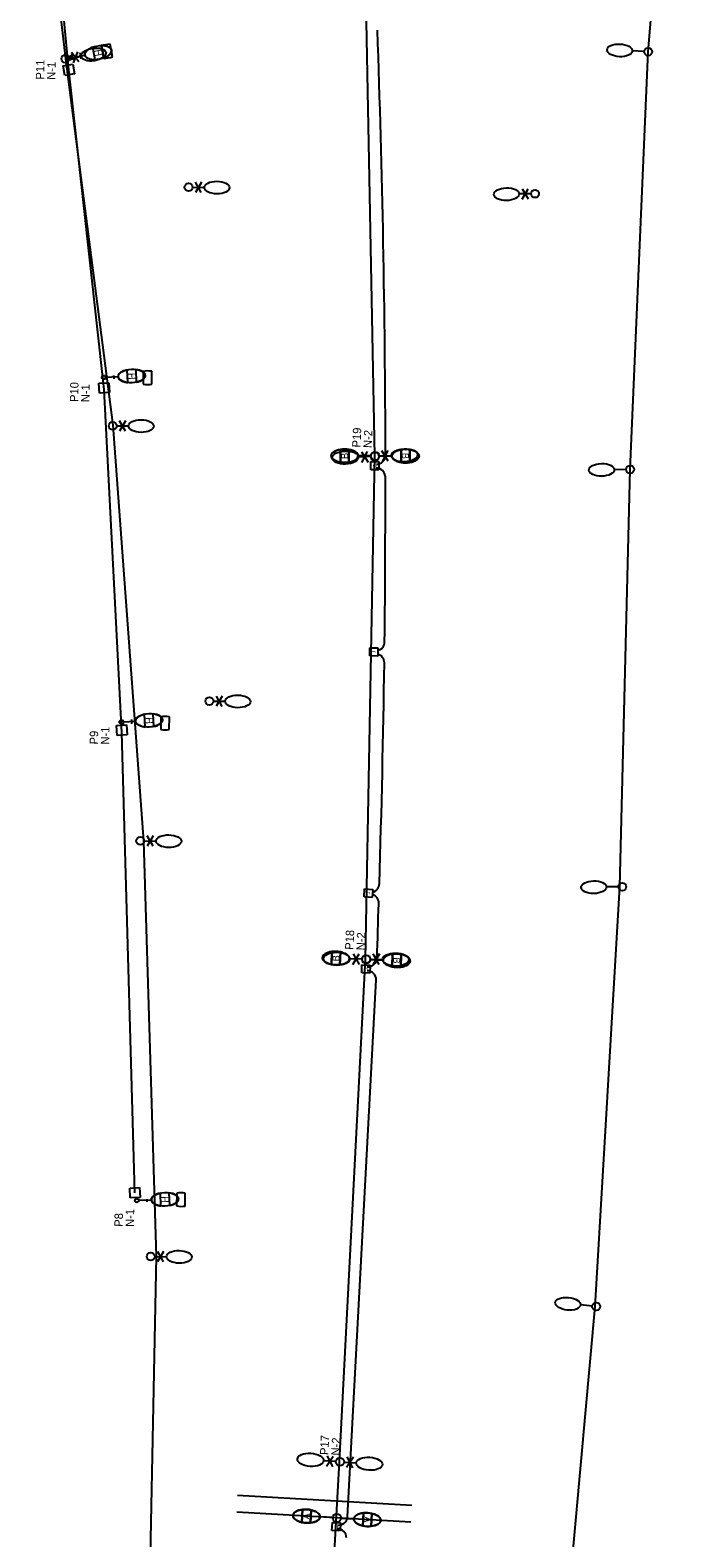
# Model space of a CAD drawing. Extents: x 925407 to 930994, y 604905 to 637063.
# Drawn here: x 929630 to 930028, y 609160 to 610061 of the extents above; entities that cross this region are included whole.
import ezdxf

# ---------------------------------------------------------------- set-up
doc = ezdxf.new("R2010")
doc.units = 0
for name, color, linetype in [('ActivePointCell_dp', 7, 'Continuous'), ('Conduit', 7, 'Continuous'), ('ConduitOT', 7, 'Continuous'), ('LiteCond_ep', 7, 'Continuous'), ('Miscellaneous2', 7, 'Continuous'), ('Miscellaneous9', 7, 'Continuous'), ('PoleLight', 7, 'Continuous'), ('PoleLight_ep', 7, 'Continuous'), ('PullBox', 7, 'Continuous')]:
    doc.layers.add(name, color=color, linetype=linetype)

msp = doc.modelspace()

# ---------------------------------------------------------------- linework, layer by layer
at = {"layer": 'ActivePointCell_dp'}
for p, q in [((929655.75, 610043.5), (929655.25, 610047.18)), ((929660.7, 610044.16), (929660.21, 610047.84)), ((929675.46, 609852.54), (929675.36, 609854.56)), ((929680.46, 609852.8), (929680.35, 609854.82)), ((929686.06, 609646.41), (929685.93, 609648.96)), ((929691.05, 609646.66), (929690.92, 609649.22)), ((929695.22, 609360.91), (929695.22, 609362.5)), ((929700.22, 609360.92), (929700.22, 609362.51)), ((929858.32, 609179.34), (929754.23, 609185.22)), ((929857.75, 609169.36), (929753.67, 609175.24))]:
    msp.add_line(p, q, dxfattribs=at)
at = {"layer": 'Conduit'}
for p, q in [((929999.47, 610048.38), (930027.95, 610398.52)), ((929988.71, 609798.68), (929999.47, 610048.38)), ((929982.61, 609549.14), (929988.71, 609798.68)), ((929967.83, 609298.26), (929982.61, 609549.14))]:
    msp.add_line(p, q, dxfattribs=at)
at = {"layer": 'ConduitOT'}
for p, q in [((929653.36, 610037.56), (929636.27, 610218.27)), ((929674.57, 609846.54), (929653.36, 610037.56)), ((929684.95, 609641.34), (929674.57, 609846.54)), ((929692.89, 609366.24), (929684.95, 609641.34)), ((929819.93, 609172.4), (929837.08, 609493.53))]:
    msp.add_line(p, q, dxfattribs=at)
for centre, radius, start, end in [((922203.17, 609789.01), 7639.44, 0.137669, 2.042639), ((929837.18, 609807.26), 5.5, 269.49023, 359.64309), ((929836.96, 609794.07), 5.5, 0.11193, 90.26479), ((922203.04, 609777.74), 7639.44, 359.384428, 0.122612), ((929836.54, 609695.73), 5.5, 285.60629, 359.29984), ((929836.38, 609683.07), 5.5, 359.20485, 72.64276), ((922203.17, 609789.01), 7639.44, 358.215061, 359.204855), ((929833.41, 609551.23), 5.5, 284.76735, 358.21506), ((929833.03, 609539.34), 5.5, 358.12573, 71.93297), ((922202.54, 609768.82), 7639.44, 358.032417, 358.277239), ((929831.98, 609506.85), 5.5, 266.51903, 356.67188), ((929831.58, 609493.47), 5.5, 0.11193, 90.26479), ((922201.34, 609731.26), 7639.44, 358.215061, 358.216886), ((929814.46, 609173.03), 5.5, 263.26846, 353.42131), ((929813.72, 609159.92), 5.5, 0.11193, 90.26479)]:
    msp.add_arc(centre, radius, start, end, dxfattribs=at)
at = {"layer": 'LiteCond_ep'}
for p, q in [((929630.28, 610222.78), (929651.34, 610044.22)), ((929651.34, 610044.22), (929679.66, 609825.12)), ((929679.66, 609825.12), (929697.97, 609576.52)), ((929697.97, 609576.52), (929705.59, 609328.04)), ((929705.59, 609328.04), (929700.69, 609087.92)), ((929945.17, 609049.26), (929967.83, 609298.26))]:
    msp.add_line(p, q, dxfattribs=at)
msp.add_lwpolyline([(929761.96, 608002.93), (929764.99, 608303.01), (929781.87, 608603.48), (929797.97, 608896.18), (929815.17, 609205.52), (929830.71, 609505.82), (929836.14, 609806.66), (929830.32, 610108.12), (929822.99, 610409.48)], dxfattribs=at)
at = {"layer": 'Miscellaneous2'}
for p, q in [((929672.97, 610051.95), (929674.39, 610044.42)), ((929679.41, 610045.37), (929677.98, 610052.9)), ((929674.39, 610044.42), (929674.39, 610044.42)), ((929679.41, 610045.37), (929679.41, 610045.37)), ((929697.81, 609857.31), (929697.88, 609849.64)), ((929702.98, 609849.69), (929702.91, 609857.35)), ((929697.88, 609849.64), (929697.88, 609849.64)), ((929702.98, 609849.69), (929702.98, 609849.69)), ((929815.61, 609810.64), (929815.59, 609802.97)), ((929815.59, 609802.97), (929815.59, 609802.97)), ((929820.69, 609802.96), (929820.71, 609810.63)), ((929820.69, 609802.96), (929820.69, 609802.96)), ((929851.96, 609810.55), (929851.94, 609802.89)), ((929851.94, 609802.89), (929851.94, 609802.89)), ((929857.04, 609802.88), (929857.06, 609810.54)), ((929857.04, 609802.88), (929857.04, 609802.88)), ((929708.33, 609650.88), (929708.25, 609643.21)), ((929713.35, 609643.16), (929713.43, 609650.82)), ((929708.25, 609643.21), (929708.25, 609643.21)), ((929713.35, 609643.16), (929713.35, 609643.16)), ((929810.52, 609510.39), (929810.22, 609502.73)), ((929810.52, 609510.39), (929810.52, 609510.39)), ((929815.32, 609502.54), (929815.61, 609510.2)), ((929815.61, 609510.2), (929815.61, 609510.2)), ((929846.84, 609509.01), (929846.55, 609501.35)), ((929846.84, 609509.01), (929846.84, 609509.01)), ((929851.65, 609501.15), (929851.94, 609508.81)), ((929851.94, 609508.81), (929851.94, 609508.81)), ((929717.86, 609365.99), (929717.78, 609358.33)), ((929722.88, 609358.28), (929722.96, 609365.94)), ((929717.78, 609358.33), (929717.78, 609358.33)), ((929722.88, 609358.28), (929722.88, 609358.28)), ((929793.07, 609176.85), (929792.64, 609169.2)), ((929793.07, 609176.85), (929793.07, 609176.85)), ((929797.73, 609168.91), (929798.16, 609176.56)), ((929798.16, 609176.56), (929798.16, 609176.56)), ((929829.36, 609174.8), (929828.93, 609167.15)), ((929829.36, 609174.8), (929829.36, 609174.8)), ((929834.02, 609166.86), (929834.46, 609174.51)), ((929834.46, 609174.51), (929834.46, 609174.51))]:
    msp.add_line(p, q, dxfattribs=at)
for centre, major_axis, start_param, end_param in [((929676.19, 610048.66), (-7.94, -1.5), 4.391271, 5.033538), ((929676.19, 610048.66), (-7.94, -1.5), 4.391241, 4.391271), ((929676.19, 610048.66), (-7.94, -1.5), 1.249648, 1.891946), ((929700.39, 609853.5), (-8.08, -0.07), 4.391271, 5.033538), ((929700.39, 609853.5), (-8.08, -0.07), 4.391241, 4.391271), ((929700.39, 609853.5), (-8.08, -0.07), 1.249648, 1.891946), ((929818.15, 609806.8), (-8.08, 0.02), 1.249648, 1.891946), ((929818.15, 609806.8), (-8.08, 0.02), 4.391271, 5.033538), ((929818.15, 609806.8), (-8.08, 0.02), 4.391241, 4.391271), ((929854.5, 609806.71), (-8.08, 0.02), 1.249648, 1.891946), ((929854.5, 609806.71), (-8.08, 0.02), 4.391271, 5.033538), ((929854.5, 609806.71), (-8.08, 0.02), 4.391241, 4.391271), ((929710.84, 609647.02), (-8.08, 0.08), 4.391271, 5.033538), ((929710.84, 609647.02), (-8.08, 0.08), 4.391241, 4.391271), ((929710.84, 609647.02), (-8.08, 0.08), 1.249648, 1.891946), ((929812.92, 609506.47), (8.07, -0.31), 1.249648, 1.891946), ((929849.24, 609505.08), (8.07, -0.31), 1.249648, 1.891946), ((929812.92, 609506.47), (8.07, -0.31), 4.391241, 4.391271), ((929812.92, 609506.47), (8.07, -0.31), 4.391271, 5.033538), ((929849.24, 609505.08), (8.07, -0.31), 4.391241, 4.391271), ((929849.24, 609505.08), (8.07, -0.31), 4.391271, 5.033538), ((929720.37, 609362.14), (-8.08, 0.08), 4.391271, 5.033538), ((929720.37, 609362.14), (-8.08, 0.08), 4.391241, 4.391271), ((929720.37, 609362.14), (-8.08, 0.08), 1.249648, 1.891946), ((929795.4, 609172.88), (8.07, -0.46), 1.249648, 1.891946), ((929831.69, 609170.83), (8.07, -0.46), 1.249648, 1.891946), ((929795.4, 609172.88), (8.07, -0.46), 4.391241, 4.391271), ((929795.4, 609172.88), (8.07, -0.46), 4.391271, 5.033538), ((929831.69, 609170.83), (8.07, -0.46), 4.391241, 4.391271), ((929831.69, 609170.83), (8.07, -0.46), 4.391271, 5.033538)]:
    msp.add_ellipse(centre, major_axis=major_axis, ratio=0.5, start_param=start_param, end_param=end_param, dxfattribs=at)
at = {"layer": 'PoleLight'}
for p, q in [((929654.32, 610044.74), (929663.01, 610046.37)), ((929669.16, 610043.63), (929667.73, 610051.16)), ((929672.74, 610052.11), (929674.17, 610044.58)), ((929688.56, 609850.58), (929688.22, 609858.24)), ((929693.32, 609858.46), (929693.66, 609850.81)), ((929675.3, 609853.83), (929682.87, 609854.16)), ((929815.59, 609802.97), (929815.61, 609810.64)), ((929820.71, 609810.63), (929820.69, 609802.96)), ((929833.8, 609806.76), (929826.23, 609806.78)), ((929838.85, 609806.75), (929846.42, 609806.73)), ((929851.94, 609802.89), (929851.96, 609810.55)), ((929857.06, 609810.54), (929857.04, 609802.88)), ((929698.96, 609644.69), (929698.55, 609652.35)), ((929703.64, 609652.62), (929704.05, 609644.96)), ((929685.67, 609647.83), (929693.23, 609648.23)), ((929810.22, 609502.73), (929810.52, 609510.39)), ((929815.61, 609510.2), (929815.32, 609502.54)), ((929828.56, 609505.87), (929820.99, 609506.16)), ((929833.6, 609505.68), (929841.17, 609505.39)), ((929846.55, 609501.35), (929846.84, 609509.01)), ((929851.94, 609508.81), (929851.65, 609501.15)), ((929695.1, 609361.75), (929702.67, 609362.02)), ((929708.33, 609358.39), (929708.06, 609366.05)), ((929713.15, 609366.23), (929713.43, 609358.57)), ((929792.64, 609169.2), (929793.07, 609176.85)), ((929798.16, 609176.56), (929797.73, 609168.91)), ((929811.03, 609172), (929803.47, 609172.42)), ((929816.07, 609171.71), (929823.63, 609171.29)), ((929828.93, 609167.15), (929829.36, 609174.8)), ((929834.46, 609174.51), (929834.02, 609166.86))]:
    msp.add_line(p, q, dxfattribs=at)
for centre, radius in [((929654.32, 610044.74), 1.14), ((929674.22, 609853.7), 1.14), ((929836.32, 609806.76), 2.52), ((929836.32, 609806.76), 2.52), ((929684.75, 609647.69), 1.14), ((929831.08, 609505.77), 2.52), ((929831.08, 609505.77), 2.52), ((929693.98, 609361.63), 1.14), ((929813.55, 609171.86), 2.52), ((929813.55, 609171.86), 2.52)]:
    msp.add_circle(centre, radius, dxfattribs=at)
for centre, major_axis in [((929670.95, 610047.87), (-7.94, -1.5)), ((929690.94, 609854.52), (-8.07, -0.36)), ((929818.15, 609806.8), (-8.08, 0.02)), ((929854.5, 609806.71), (-8.08, 0.02)), ((929701.3, 609648.66), (-8.07, -0.43)), ((929812.92, 609506.47), (8.07, -0.31)), ((929849.24, 609505.08), (8.07, -0.31)), ((929710.74, 609362.31), (-8.07, -0.29)), ((929795.4, 609172.88), (8.07, -0.46)), ((929831.69, 609170.83), (8.07, -0.46))]:
    msp.add_ellipse(centre, major_axis=major_axis, ratio=0.5, dxfattribs=at)
for centre, major_axis, start_param, end_param in [((929670.95, 610047.87), (-7.94, -1.5), 5.033538, 6.283185), ((929670.95, 610047.87), (-7.94, -1.5), 0, 0.847605), ((929670.95, 610047.87), (-7.94, -1.5), 1.891945, 4.391241), ((929670.95, 610047.87), (-7.94, -1.5), 0.847605, 1.249648), ((929690.94, 609854.52), (-8.07, -0.36), 5.033538, 6.283185), ((929690.94, 609854.52), (-8.07, -0.36), 1.891945, 4.391241), ((929690.94, 609854.52), (-8.07, -0.36), 0, 0.847605), ((929690.94, 609854.52), (-8.07, -0.36), 0.847605, 1.249648), ((929818.15, 609806.8), (-8.08, 0.02), 5.033538, 6.283185), ((929818.15, 609806.8), (-8.08, 0.02), 0, 0.847605), ((929818.15, 609806.8), (-8.08, 0.02), 0.847605, 1.249648), ((929818.15, 609806.8), (-8.08, 0.02), 1.891945, 4.391241), ((929854.5, 609806.71), (-8.08, 0.02), 5.033538, 6.283185), ((929854.5, 609806.71), (-8.08, 0.02), 0, 0.847605), ((929854.5, 609806.71), (-8.08, 0.02), 0.847605, 1.249648), ((929854.5, 609806.71), (-8.08, 0.02), 1.891945, 4.391241), ((929701.3, 609648.66), (-8.07, -0.43), 5.033538, 6.283185), ((929701.3, 609648.66), (-8.07, -0.43), 1.891945, 4.391241), ((929701.3, 609648.66), (-8.07, -0.43), 0, 0.847605), ((929701.3, 609648.66), (-8.07, -0.43), 0.847605, 1.249648), ((929812.92, 609506.47), (8.07, -0.31), 1.891945, 4.391241), ((929812.92, 609506.47), (8.07, -0.31), 5.033538, 6.283185), ((929812.92, 609506.47), (8.07, -0.31), 0.847605, 1.249648), ((929812.92, 609506.47), (8.07, -0.31), 0, 0.847605), ((929849.24, 609505.08), (8.07, -0.31), 1.891945, 4.391241), ((929849.24, 609505.08), (8.07, -0.31), 5.033538, 6.283185), ((929849.24, 609505.08), (8.07, -0.31), 0.847605, 1.249648), ((929849.24, 609505.08), (8.07, -0.31), 0, 0.847605), ((929710.74, 609362.31), (-8.07, -0.29), 5.033538, 6.283185), ((929710.74, 609362.31), (-8.07, -0.29), 0, 0.847605), ((929710.74, 609362.31), (-8.07, -0.29), 1.891945, 4.391241), ((929710.74, 609362.31), (-8.07, -0.29), 0.847605, 1.249648), ((929795.4, 609172.88), (8.07, -0.46), 1.891945, 4.391241), ((929795.4, 609172.88), (8.07, -0.46), 5.033538, 6.283185), ((929795.4, 609172.88), (8.07, -0.46), 0.847605, 1.249648), ((929795.4, 609172.88), (8.07, -0.46), 0, 0.847605), ((929831.69, 609170.83), (8.07, -0.46), 1.891945, 4.391241), ((929831.69, 609170.83), (8.07, -0.46), 0.847605, 1.249648), ((929831.69, 609170.83), (8.07, -0.46), 0, 0.847605), ((929831.69, 609170.83), (8.07, -0.46), 5.033538, 6.283185)]:
    msp.add_ellipse(centre, major_axis=major_axis, ratio=0.5, start_param=start_param, end_param=end_param, dxfattribs=at)
at = {"layer": 'PoleLight_ep'}
for p, q in [((929653.67, 610044.57), (929660.67, 610045.62)), ((929659.37, 610042.33), (929654.97, 610047.87)), ((929658.47, 610048.39), (929655.88, 610041.81)), ((929997.11, 610048.5), (929990.02, 610048.86)), ((929727.27, 609967.37), (929734.33, 609967.29)), ((929732.6, 609970.37), (929729, 609964.29)), ((929732.53, 609964.25), (929729.07, 609970.41)), ((929924.15, 609966.48), (929927.8, 609960.39)), ((929924.25, 609960.33), (929927.7, 609966.53)), ((929929.52, 609963.49), (929922.43, 609963.38)), ((929681.95, 609824.71), (929689.02, 609824.66)), ((929687.28, 609827.73), (929683.69, 609821.63)), ((929687.23, 609821.6), (929683.74, 609827.76)), ((929833.76, 609806.36), (929826.41, 609806.08)), ((929828.2, 609809.3), (929832.12, 609803.07)), ((929828.44, 609802.93), (929831.87, 609809.44)), ((929838.65, 609806.55), (929846, 609806.83)), ((929844.21, 609803.62), (929840.29, 609809.84)), ((929843.97, 609809.98), (929840.54, 609803.48)), ((929986.34, 609798.64), (929979.25, 609798.53)), ((929739.72, 609660.15), (929746.78, 609660.08)), ((929745.05, 609663.15), (929741.45, 609657.08)), ((929744.98, 609657.04), (929741.52, 609663.19)), ((929703.75, 609579.58), (929700.16, 609573.48)), ((929703.7, 609573.45), (929700.21, 609579.61)), ((929698.41, 609576.56), (929705.49, 609576.5)), ((929981.64, 609549.17), (929974.55, 609549.06)), ((929828.56, 609505.92), (929821.21, 609506.01)), ((929823.08, 609502.76), (929826.83, 609509.08)), ((929823.16, 609509.13), (929826.75, 609502.72)), ((929833.46, 609505.86), (929840.8, 609505.76)), ((929838.93, 609509.01), (929835.18, 609502.69)), ((929838.85, 609502.64), (929835.26, 609509.06)), ((929704.69, 609328.05), (929711.77, 609327.99)), ((929710.03, 609331.07), (929706.44, 609324.97)), ((929709.97, 609324.94), (929706.49, 609331.1)), ((929966.13, 609298.48), (929959.07, 609299.16)), ((929807.25, 609202.71), (929811.33, 609208.82)), ((929807.66, 609209.06), (929810.91, 609202.47)), ((929823.41, 609208.1), (929819.33, 609201.99)), ((929822.99, 609201.75), (929819.75, 609208.34)), ((929812.88, 609205.57), (929805.55, 609206.05)), ((929817.77, 609205.24), (929825.11, 609204.76))]:
    msp.add_line(p, q, dxfattribs=at)
for centre, radius in [((929651.34, 610044.22), 2.36), ((929999.47, 610048.38), 2.37), ((929724.91, 609967.39), 2.35), ((929931.89, 609963.53), 2.36), ((929679.59, 609824.72), 2.36), ((929836.21, 609806.46), 2.45), ((929988.71, 609798.68), 2.37), ((929737.36, 609660.18), 2.35), ((929696.06, 609576.58), 2.36), ((929984.01, 609549.2), 2.37), ((929831.01, 609505.89), 2.45), ((929702.33, 609328.07), 2.36), ((929968.49, 609298.26), 2.37), ((929815.33, 609205.4), 2.45)]:
    msp.add_circle(centre, radius, dxfattribs=at)
for centre, major_axis in [((929668.13, 610046.75), (7.47, 1.12)), ((929982.46, 610049.24), (-7.56, 0.38)), ((929741.86, 609967.21), (7.53, -0.08)), ((929914.86, 609963.25), (-7.57, -0.13)), ((929696.57, 609824.6), (7.55, -0.05)), ((929853.83, 609807.13), (7.83, 0.3)), ((929818.58, 609805.78), (-7.83, -0.3)), ((929971.68, 609798.41), (-7.57, -0.12)), ((929754.31, 609659.99), (7.53, -0.08)), ((929713.04, 609576.43), (7.55, -0.06)), ((929966.98, 609548.94), (-7.57, -0.12)), ((929813.37, 609506.11), (-7.84, 0.1)), ((929848.64, 609505.66), (7.84, -0.1)), ((929719.32, 609327.93), (7.55, -0.06)), ((929951.53, 609299.88), (-7.54, 0.72)), ((929797.73, 609206.56), (-7.82, 0.52)), ((929832.93, 609204.24), (7.82, -0.52))]:
    msp.add_ellipse(centre, major_axis=major_axis, ratio=0.5, dxfattribs=at)
at = {"layer": 'PullBox'}
for p, q in [((929649.93, 610039.96), (929655.75, 610040.99)), ((929650.96, 610034.13), (929649.93, 610039.96)), ((929655.75, 610040.99), (929656.79, 610035.17)), ((929656.79, 610035.17), (929650.96, 610034.13)), ((929671.39, 609850.19), (929677.3, 609850.54)), ((929671.74, 609844.29), (929671.39, 609850.19)), ((929677.3, 609850.54), (929677.64, 609844.63)), ((929677.64, 609844.63), (929671.74, 609844.29)), ((929833.7, 609798.54), (929833.71, 609803.39)), ((929833.71, 609803.39), (929838.55, 609803.38)), ((929838.55, 609803.38), (929838.54, 609798.53)), ((929838.54, 609798.53), (929833.7, 609798.54)), ((929833.17, 609687.15), (929833.18, 609691.99)), ((929838.02, 609687.14), (929833.17, 609687.15)), ((929833.18, 609691.99), (929838.02, 609691.98)), ((929838.02, 609691.98), (929838.02, 609687.14)), ((929681.94, 609645.61), (929687.84, 609645.95)), ((929682.28, 609639.7), (929681.94, 609645.61)), ((929688.18, 609640.05), (929682.28, 609639.7)), ((929687.84, 609645.95), (929688.18, 609640.05)), ((929829.8, 609543.09), (929830.07, 609547.92)), ((929834.63, 609542.81), (929829.8, 609543.09)), ((929830.07, 609547.92), (929834.91, 609547.65)), ((929834.91, 609547.65), (929834.63, 609542.81)), ((929828.38, 609497.66), (929828.51, 609502.5)), ((929833.22, 609497.52), (929828.38, 609497.66)), ((929828.51, 609502.5), (929833.36, 609502.36)), ((929833.36, 609502.36), (929833.22, 609497.52)), ((929689.77, 609369.02), (929695.67, 609369.36)), ((929690.11, 609363.12), (929689.77, 609369.02)), ((929696.01, 609363.46), (929690.11, 609363.12)), ((929695.67, 609369.36), (929696.01, 609363.46)), ((929810.58, 609164.3), (929810.86, 609169.14)), ((929815.42, 609164.03), (929810.58, 609164.3)), ((929810.86, 609169.14), (929815.7, 609168.86)), ((929815.7, 609168.86), (929815.42, 609164.03))]:
    msp.add_line(p, q, dxfattribs=at)

# ---------------------------------------------------------------- texts
at = {"layer": 'ActivePointCell_dp'}
for s, rotation, p in [('P11', 89.02968, (929638.64, 610031.71)), ('N-1', 89.02968, (929645.34, 610031.6)), ('P10', 89.02968, (929658.99, 609838.98)), ('N-1', 89.02968, (929665.69, 609838.86)), ('P19', 87.34824, (929827.59, 609811.7)), ('N-2', 87.34824, (929834.28, 609811.39)), ('P9', 89.02968, (929670.78, 609634.25)), ('N-1', 89.02968, (929677.48, 609634.13)), ('P18', 87.34824, (929823.36, 609511.4)), ('N-2', 87.34824, (929830.06, 609511.09)), ('P8', 89.02968, (929685.56, 609345.88)), ('N-1', 89.02968, (929692.26, 609345.77)), ('P17', 87.34824, (929808.39, 609209.35)), ('N-2', 87.34824, (929815.09, 609209.04))]:
    msp.add_text(s, height=5, rotation=rotation, dxfattribs=at).set_placement(p)
at = {"layer": 'Miscellaneous9'}
for s, rotation, p in [('H', 280.69334, (929668.6, 610049.33)), ('H', 272.53472, (929688.82, 609856.29)), ('B', 89.86615, (929820.18, 609804.93)), ('B', 269.86615, (929852.46, 609808.58)), ('H', 273.04458, (929699.17, 609650.41)), ('B', 87.81469, (929814.89, 609504.53)), ('B', 267.81469, (929847.28, 609507.02)), ('H', 272.06368, (929708.64, 609364.1)), ('A', 86.76665, (929797.33, 609170.87)), ('A', 266.76665, (929829.77, 609172.84))]:
    msp.add_text(s, height=4.08, rotation=rotation, dxfattribs=at).set_placement(p)
at = {"layer": 'PullBox'}
for rotation, p in [(89.89191, (929837.09, 609800.3)), (89.89191, (929836.57, 609688.91)), (86.76662, (929833.28, 609544.66)), (88.39191, (929831.82, 609499.33)), (86.76662, (929814.07, 609165.87))]:
    msp.add_text('J', height=1.94, rotation=rotation, dxfattribs=at).set_placement(p)

doc.saveas('drawing.dxf')
